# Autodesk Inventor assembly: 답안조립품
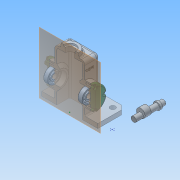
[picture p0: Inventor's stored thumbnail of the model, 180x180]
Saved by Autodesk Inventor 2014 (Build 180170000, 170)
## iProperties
Created: 2016-02
Part Number: 답안조립품
Document SubType Name: Assembly
Designer: nert
Author: nert
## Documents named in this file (7)
- C:\Users\nert\Desktop\460211V1011\답안조립품.iam
- C:\Users\nert\Desktop\460211V1011\본체.ipt
- C:\Users\nert\Desktop\460211V1011\뒤커버.ipt
- C:\Users\nert\Desktop\460211V1011\베어링 12 x 32 x 10.ipt
- C:\Users\nert\Desktop\460211V1011\앞커버.ipt
- C:\Users\nert\Desktop\460211V1011\편심축.ipt
- C:\Users\nert\Desktop\460211V1011\키 4 x 4 x 10.ipt
